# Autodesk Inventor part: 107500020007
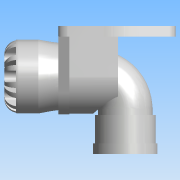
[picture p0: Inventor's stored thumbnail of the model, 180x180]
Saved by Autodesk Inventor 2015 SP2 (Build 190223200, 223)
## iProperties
Created: 2017-01
Part Number: 107500020007
Material: PVC-Piping
Description: PLASSON WALL PLATE ELBOW 20X3/4" SERIES 1
Document SubType Name: Modeling
Designer: Кирилл
Mass: 122.736 g
Surface Area: 365.546 cm^2
Volume: 87.6688 cm^3
Density: 1.4 g/cm^3
Appearance: Smooth - White
Author: KIM
Author: naamad
Title: SR1-ELBOW-BRACKET-20-CAT
Organization: PLASSON
Sending System: PRO/ENGINEER BY PARAMETRIC TECHNOLOGY CORPORATION, 2014000
Preprocessor: PRO/ENGINEER BY PARAMETRIC TECHNOLOGY CORPORATION, 2014000
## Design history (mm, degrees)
derived "1075.ipt"
feature "Solid1::1075.ipt"
feature "Solid8::1075.ipt"
feature "Solid11::1075.ipt"
tag "TaggingFeature1"
body "Solid1"
body "Solid2"
body "Solid3"
other parameters: "d4" = 41, "d5" = 25, "d6" = 18.9, "d7" = 45, "d9" = 36.08, "d13" = 3.96, "d14" = 7.92, "d24" = 43, "d26" = 67, "d29" = 30.38742, "d31" = 0, "d32" = 0, "d39" = 6.4, "d41" = 6.4, "d42" = 0, "d44" = 360 deg, "d46" = 8 deg, "d47" = 8 deg, "d48" = 0.4, "d49" = 0.4, "d51" = 0, "d53" = 360 deg, "d55" = 0.2, "d61" = 2, "d65" = 2.84629, "d69" = 90 deg, "d71" = 4.658, "d72" = 0, "d73" = 0, "d74" = 5.5, "d78" = 28, "d79" = 36.5, "d80" = 95, "d81" = 6, "d82" = 0, "d83" = 6, "d84" = 0, "d87" = 27, "d88" = 0, "d89" = 27, "d90" = 0, "d91" = 28, "d93" = 95, "d94" = 36.5, "d95" = 6, "d96" = 0, "d98" = 6, "d99" = 0, "d100" = 4.5, "d101" = 19, "d102" = 29, "d103" = 0, "d105" = 0, "d107" = 0, "d108" = 24.117, "d109" = 4.8234, "d110" = 0.96468, "d111" = 18, "d112" = 21.6, "d113" = 21.7053, "d114" = 6, "Rp_" = 24.117, "E_" = 41, "l_" = 45, "l_2" = 18, "A_" = 67, "A_1" = 43, "A_2" = 28, "L_" = 73, "H_" = 95, "d30" = 33.7638, "d37" = 25, "d38" = 41, "d40" = 8
